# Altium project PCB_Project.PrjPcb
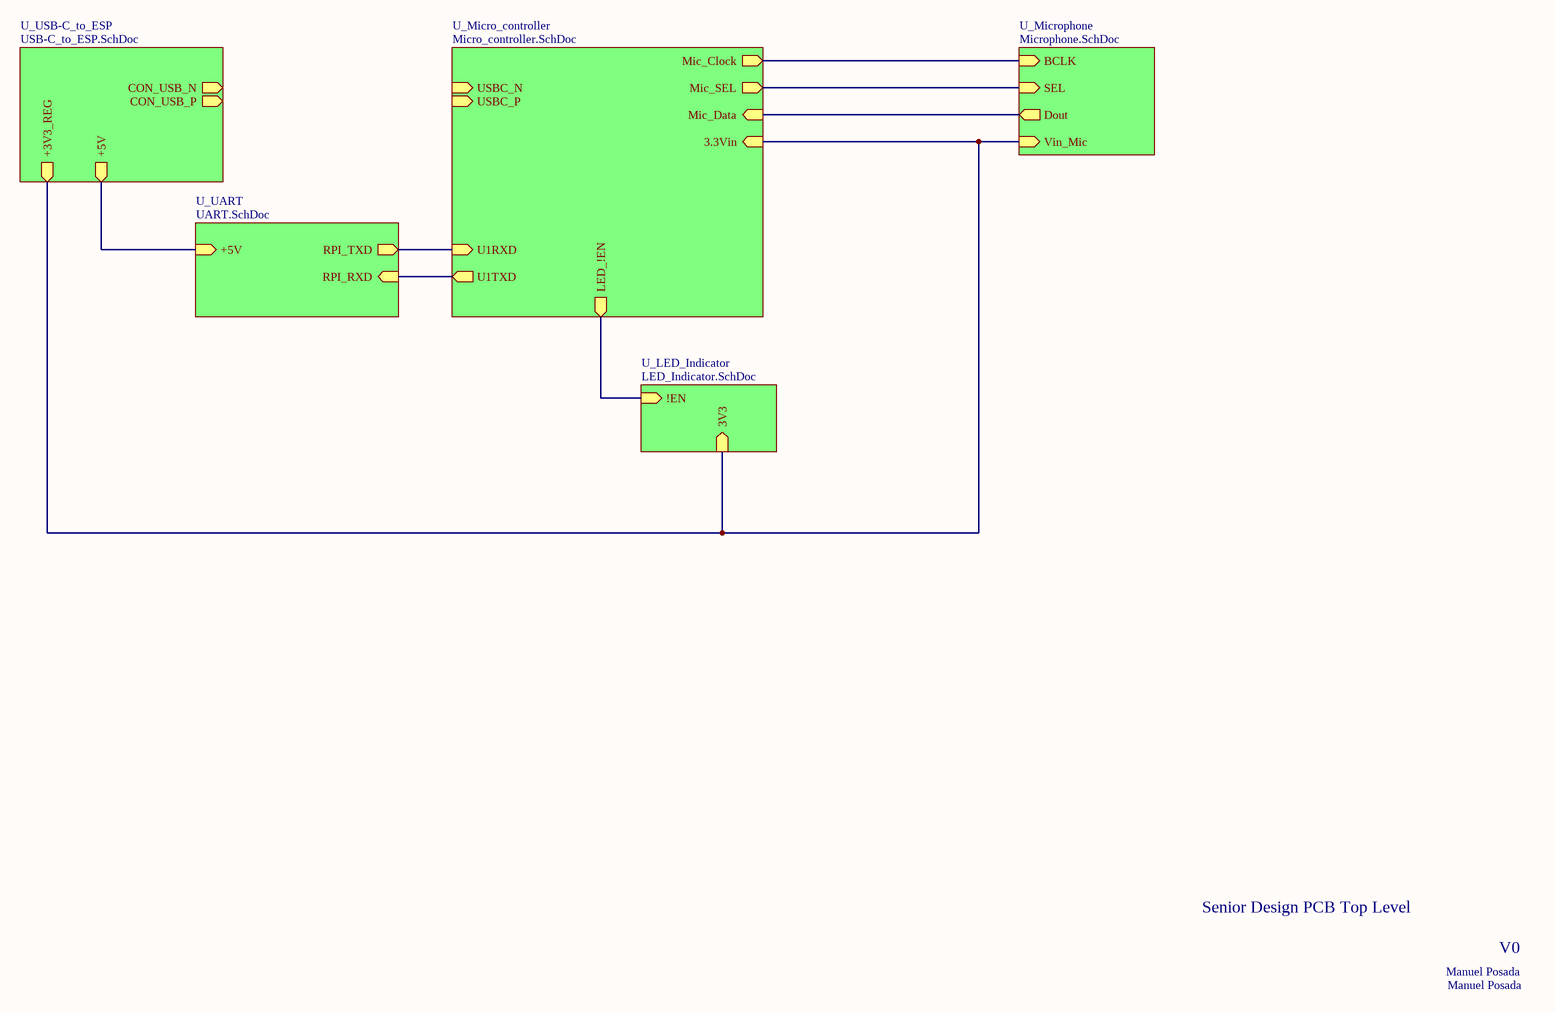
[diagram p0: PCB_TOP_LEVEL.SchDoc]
6 sheets, 64 parts. Net scope: hierarchical (ports join the sheet entries above them; power ports are global).
Sheets:
  PCB_TOP_LEVEL.SchDoc
    U_Micro_controller = Micro_controller.SchDoc
    U_USB-C_to_ESP = USB-C_to_ESP.SchDoc
    U_Microphone = Microphone.SchDoc
    U_UART = UART.SchDoc
    U_LED_Indicator = LED_Indicator.SchDoc

## Sheet PCB_TOP_LEVEL.SchDoc
size B; SheetNumber: 1; SheetTotal: 6

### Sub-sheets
U_LED_Indicator = LED_Indicator.SchDoc: 3V3 (in), !EN (in)
U_Micro_controller = Micro_controller.SchDoc: 3.3Vin (in), Mic_Data (in), Mic_SEL (out), Mic_Clock (out), U1TXD (out), U1RXD (in), LED_!EN (out), USBC_N (in), USBC_P (in)
U_Microphone = Microphone.SchDoc: Vin_Mic (in), BCLK (in), Dout (out), SEL (in)
U_UART = UART.SchDoc: +5V (in), RPI_RXD (in), RPI_TXD (out)
U_USB-C_to_ESP = USB-C_to_ESP.SchDoc: +3V3_REG (out), +5V (out), CON_USB_N (out), CON_USB_P (out)

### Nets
+3V3_REG: sheet U_Micro_controller/3.3Vin, sheet U_USB-C_to_ESP/+3V3_REG, sheet U_Microphone/Vin_Mic, sheet U_LED_Indicator/3V3
GPIO3: sheet U_Micro_controller/LED_!EN, sheet U_LED_Indicator/!EN
GPIO4: sheet U_Micro_controller/Mic_Data, sheet U_Microphone/Dout
GPIO5: sheet U_Micro_controller/Mic_SEL, sheet U_Microphone/SEL
GPIO17: sheet U_Micro_controller/U1TXD, sheet U_UART/RPI_RXD
GPIO18: sheet U_Micro_controller/U1RXD, sheet U_UART/RPI_TXD
GPIO41: sheet U_Micro_controller/Mic_Clock, sheet U_Microphone/BCLK
NetJ4_1: sheet U_USB-C_to_ESP/+5V, sheet U_UART/+5V

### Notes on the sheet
- Senior Design PCB Top Level
- Manuel Posada
- V0

## Sheet Micro_controller.SchDoc
size C; SheetNumber: 3; SheetTotal: 6
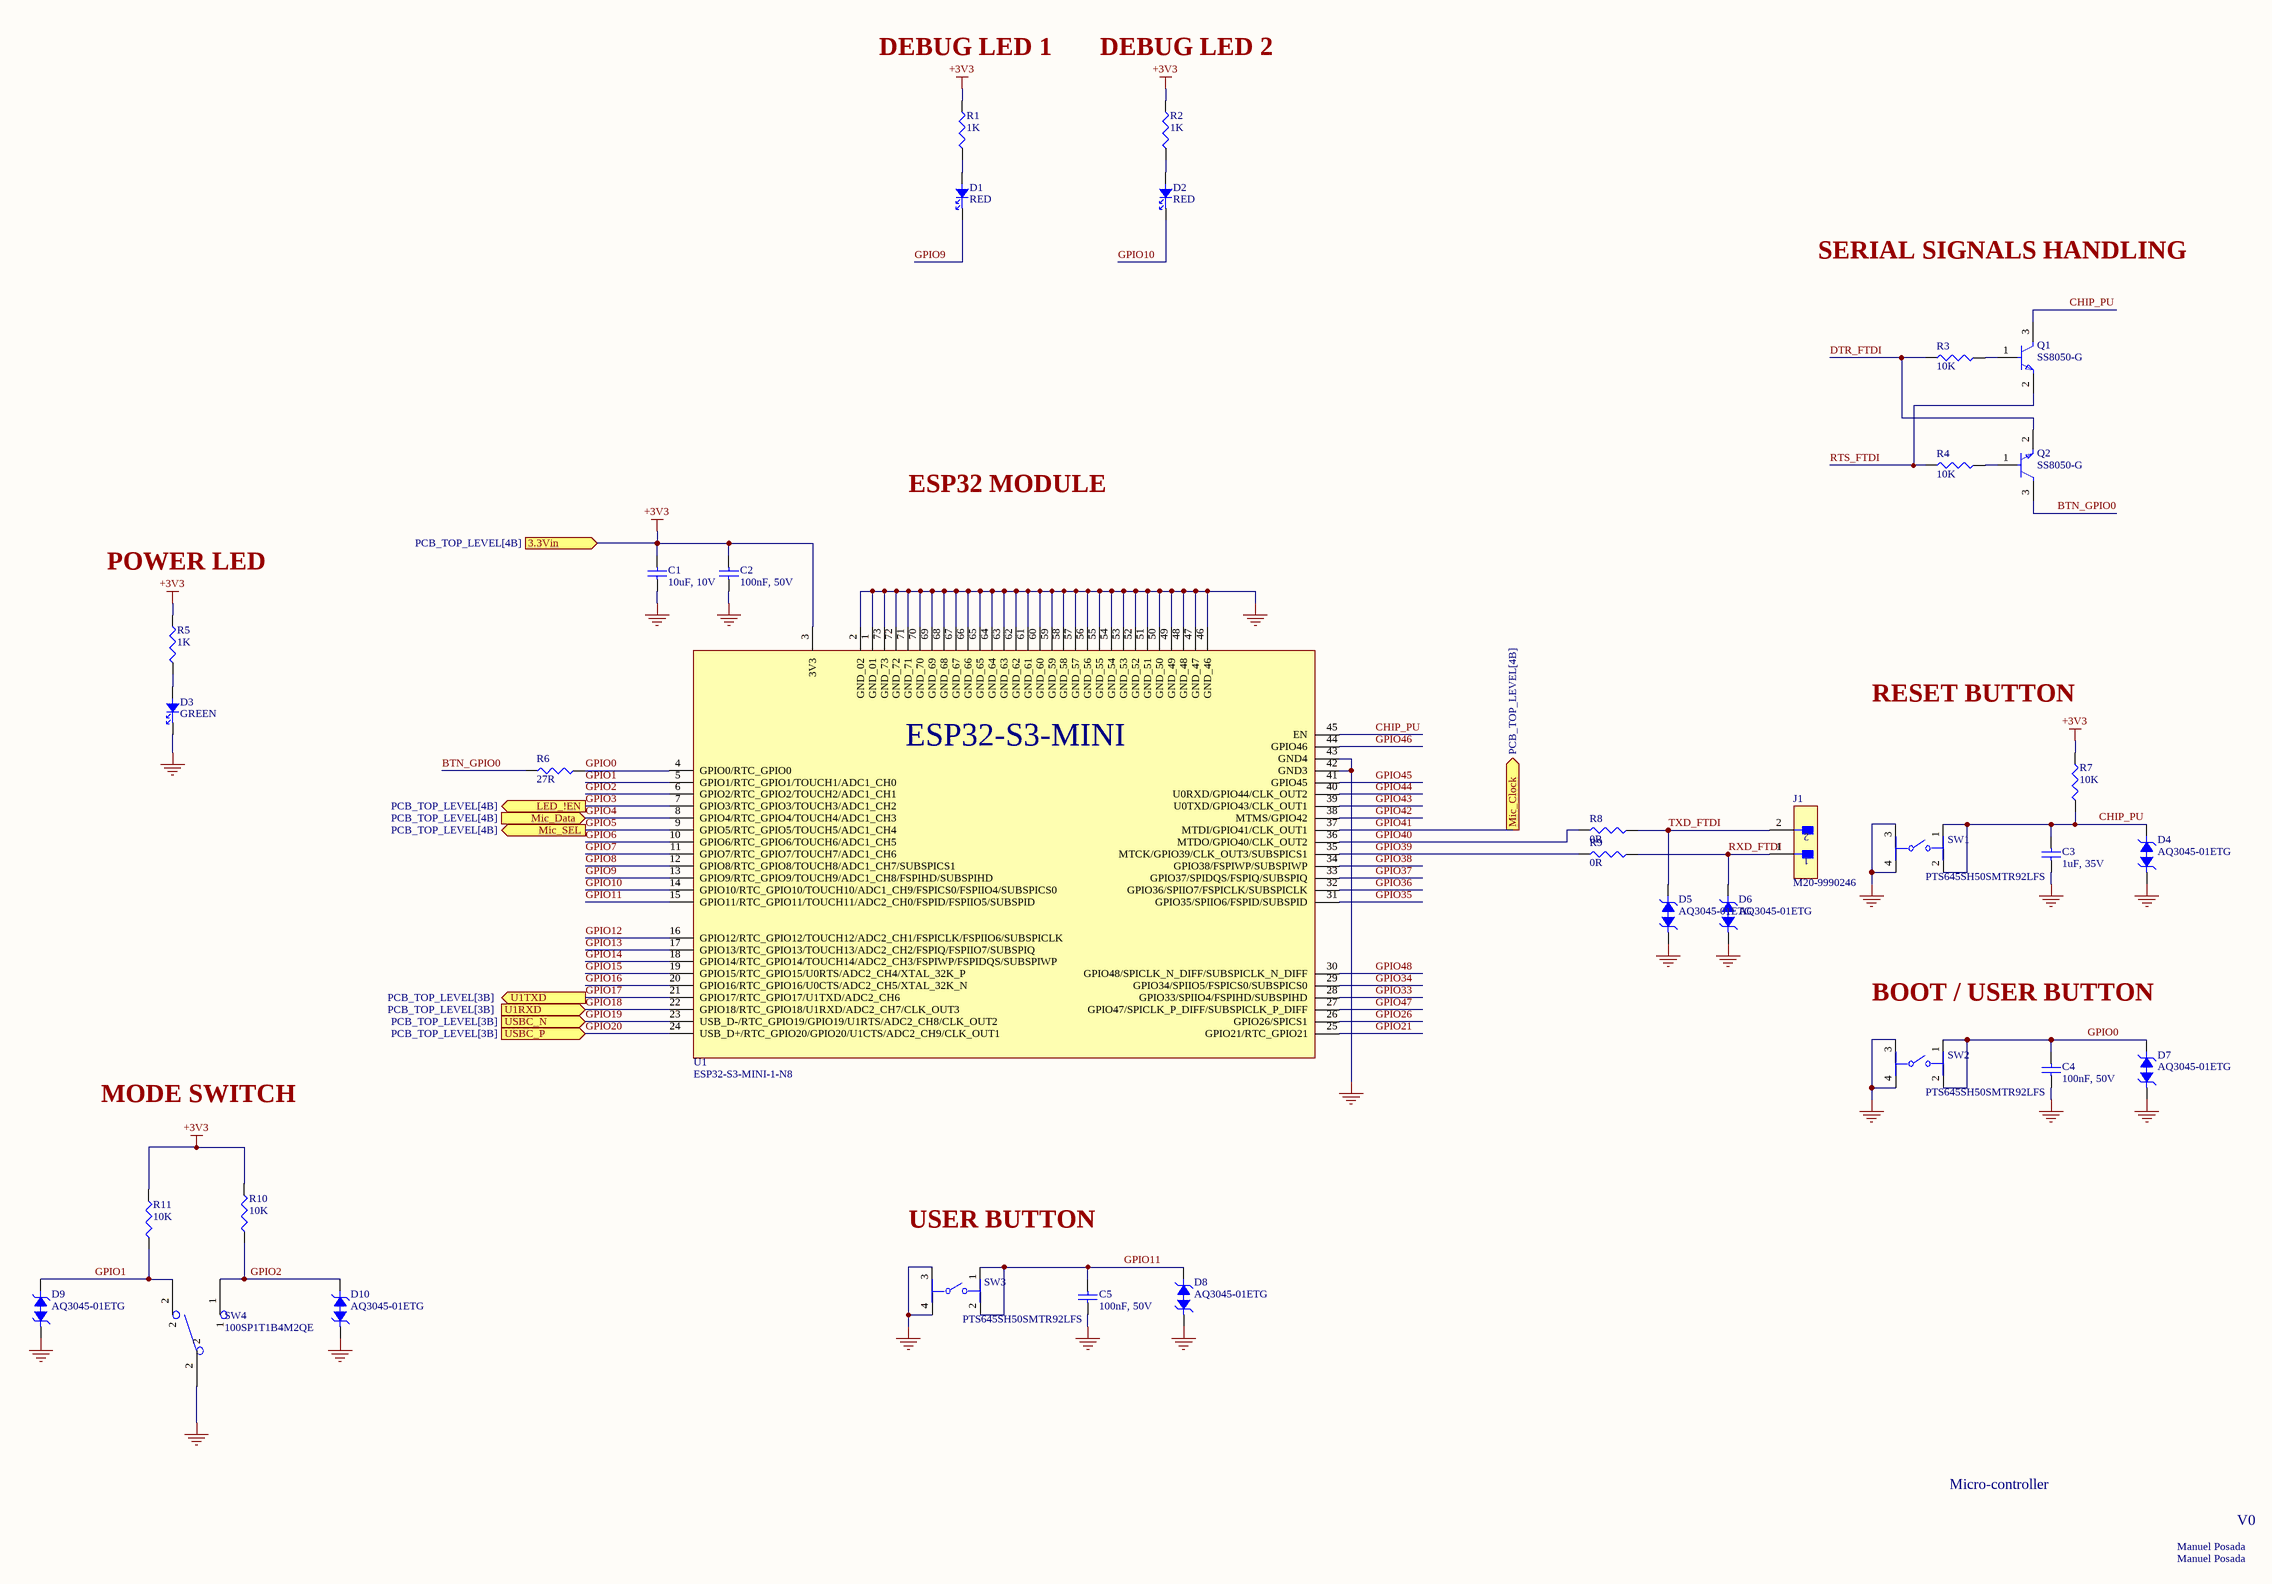
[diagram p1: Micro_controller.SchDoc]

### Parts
C1  10uF, 10V  [CAPC1005X55N]
C2  100nF, 50V  [CAPC1005X55N]
C3  1uF, 35V  [CAPC1005X55N]
C4  100nF, 50V  [CAPC1005X55N]
C5  100nF, 50V  [CAPC1005X55N]
D1  RED  [LED0402R]
D2  RED  [LED0402R]
D3  GREEN  [LED0402G]
D4  AQ3045-01ETG  [SOD882]
D5  AQ3045-01ETG  [SOD882]
D6  AQ3045-01ETG  [SOD882]
D7  AQ3045-01ETG  [SOD882]
D8  AQ3045-01ETG  [SOD882]
D9  AQ3045-01ETG  [SOD882]
D10  AQ3045-01ETG  [SOD882]
J1  M20-9990246
Q1  SS8050-G  [FP-SS8050-G-IPC_B]
Q2  SS8050-G  [FP-SS8050-G-IPC_B]
R1  1K  [RESC1005X37N]
R2  1K  [RESC1005X37N]
R3  10K  [RESC1005X37N]
R4  10K  [RESC1005X37N]
R5  1K  [RESC1005X37N]
R6  27R  [RESC1005X37N]
R7  10K  [RESC1005X37N]
R8  0R  [RESC1005X37N]
R9  0R  [RESC1005X37N]
R10  10K  [RESC1005X37N]
R11  10K  [RESC1005X37N]
SW1  PTS645SH50SMTR92LFS  [FP-PTS645SH50SMTR92LFS-MFG]
SW2  PTS645SH50SMTR92LFS  [FP-PTS645SH50SMTR92LFS-MFG]
SW3  PTS645SH50SMTR92LFS  [FP-PTS645SH50SMTR92LFS-MFG]
SW4  100SP1T1B4M2QE
U1  ESP32-S3-MINI-1-N8  [XCVR_ESP32-S3-MINI-1-N8]

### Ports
3.3Vin (in, see PCB_TOP_LEVEL[4B]), LED_!EN (out, see PCB_TOP_LEVEL[4B]), Mic_Clock (out, see PCB_TOP_LEVEL[4B]), Mic_Data (in, see PCB_TOP_LEVEL[4B]), Mic_SEL (out, see PCB_TOP_LEVEL[4B]), U1RXD (in, see PCB_TOP_LEVEL[3B]), U1TXD (out, see PCB_TOP_LEVEL[3B]), USBC_N (in, see PCB_TOP_LEVEL[3B]), USBC_P (in, see PCB_TOP_LEVEL[3B])

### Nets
+3V3: C1.2 C2.2 R1.2 R2.2 R5.2 R7.2 R10.1 R11.1 U1.3(3V3) ; port 3.3Vin  [project net +3V3_REG]
GND: C1.1 C2.1 C3.1 C4.1 C5.1 D3.1 D4.1 D5.1 D6.1 D7.1 D8.1 D9.1 D10.1 SW1.3 SW1.4 SW2.3 SW2.4 SW3.3 SW3.4 SW4.2 U1.1(GND_01) U1.2(GND_02) U1.42(GND3) U1.43(GND4) U1.46(GND_46) U1.47(GND_47) U1.48(GND_48) U1.49(GND_49) U1.50(GND_50) U1.51(GND_51) U1.52(GND_52) U1.53(GND_53) U1.54(GND_54) U1.55(GND_55) U1.56(GND_56) U1.57(GND_57) U1.58(GND_58) U1.59(GND_59) U1.60(GND_60) U1.61(GND_61) U1.62(GND_62) U1.63(GND_63) U1.64(GND_64) U1.65(GND_65) U1.66(GND_66) U1.67(GND_67) U1.68(GND_68) U1.69(GND_69) U1.70(GND_70) U1.71(GND_71) U1.72(GND_72) U1.73(GND_73)
BTN_GPIO0: Q2.3(C) R6.1
CHIP_PU: C3.2 D4.2 Q1.3(C) R7.1 SW1.1 SW1.2 U1.45(EN)
DTR_FTDI: Q2.2(E) R3.1
GPIO0: C4.2 D7.2 R6.2 SW2.1 SW2.2 U1.4(GPIO0/RTC_GPIO0)
GPIO1: D9.2 R11.2 SW4.2 U1.5(GPIO1/RTC_GPIO1/TOUCH1/ADC1_CH0)
GPIO2: D10.2 R10.2 SW4.1 U1.6(GPIO2/RTC_GPIO2/TOUCH2/ADC1_CH1)
GPIO3: U1.7(GPIO3/RTC_GPIO3/TOUCH3/ADC1_CH2) ; port LED_!EN
GPIO4: U1.8(GPIO4/RTC_GPIO4/TOUCH4/ADC1_CH3) ; port Mic_Data
GPIO5: U1.9(GPIO5/RTC_GPIO5/TOUCH5/ADC1_CH4) ; port Mic_SEL
GPIO6: U1.10(GPIO6/RTC_GPIO6/TOUCH6/ADC1_CH5)
GPIO7: U1.11(GPIO7/RTC_GPIO7/TOUCH7/ADC1_CH6)
GPIO8: U1.12(GPIO8/RTC_GPIO8/TOUCH8/ADC1_CH7/SUBSPICS1)
GPIO9: D1.1 U1.13(GPIO9/RTC_GPIO9/TOUCH9/ADC1_CH8/FSPIHD/SUBSPIHD)
GPIO10: D2.1 U1.14(GPIO10/RTC_GPIO10/TOUCH10/ADC1_CH9/FSPICS0/FSPIIO4/SUBSPICS0)
GPIO11: C5.2 D8.2 SW3.1 SW3.2 U1.15(GPIO11/RTC_GPIO11/TOUCH11/ADC2_CH0/FSPID/FSPIIO5/SUBSPID)
GPIO12: U1.16(GPIO12/RTC_GPIO12/TOUCH12/ADC2_CH1/FSPICLK/FSPIIO6/SUBSPICLK)
GPIO13: U1.17(GPIO13/RTC_GPIO13/TOUCH13/ADC2_CH2/FSPIQ/FSPIIO7/SUBSPIQ)
GPIO14: U1.18(GPIO14/RTC_GPIO14/TOUCH14/ADC2_CH3/FSPIWP/FSPIDQS/SUBSPIWP)
GPIO15: U1.19(GPIO15/RTC_GPIO15/U0RTS/ADC2_CH4/XTAL_32K_P)
GPIO16: U1.20(GPIO16/RTC_GPIO16/U0CTS/ADC2_CH5/XTAL_32K_N)
GPIO17: U1.21(GPIO17/RTC_GPIO17/U1TXD/ADC2_CH6) ; port U1TXD
GPIO18: U1.22(GPIO18/RTC_GPIO18/U1RXD/ADC2_CH7/CLK_OUT3) ; port U1RXD
GPIO19: U1.23(USB_D-/RTC_GPIO19/GPIO19/U1RTS/ADC2_CH8/CLK_OUT2) ; port USBC_N
GPIO20: U1.24(USB_D+/RTC_GPIO20/GPIO20/U1CTS/ADC2_CH9/CLK_OUT1) ; port USBC_P
GPIO21: U1.25(GPIO21/RTC_GPIO21)
GPIO26: U1.26(GPIO26/SPICS1)
GPIO33: U1.28(GPIO33/SPIIO4/FSPIHD/SUBSPIHD)
GPIO34: U1.29(GPIO34/SPIIO5/FSPICS0/SUBSPICS0)
GPIO35: U1.31(GPIO35/SPIIO6/FSPID/SUBSPID)
GPIO36: U1.32(GPIO36/SPIIO7/FSPICLK/SUBSPICLK)
GPIO37: U1.33(GPIO37/SPIDQS/FSPIQ/SUBSPIQ)
GPIO38: U1.34(GPIO38/FSPIWP/SUBSPIWP)
GPIO39: R9.1 U1.35(MTCK/GPIO39/CLK_OUT3/SUBSPICS1)
GPIO40: R8.1 U1.36(MTDO/GPIO40/CLK_OUT2)
GPIO41: U1.37(MTDI/GPIO41/CLK_OUT1) ; port Mic_Clock
GPIO42: U1.38(MTMS/GPIO42)
GPIO43: U1.39(U0TXD/GPIO43/CLK_OUT1)
GPIO44: U1.40(U0RXD/GPIO44/CLK_OUT2)
GPIO45: U1.41(GPIO45)
GPIO46: U1.44(GPIO46)
GPIO47: U1.27(GPIO47/SPICLK_P_DIFF/SUBSPICLK_P_DIFF)
GPIO48: U1.30(GPIO48/SPICLK_N_DIFF/SUBSPICLK_N_DIFF)
RTS_FTDI: Q1.2(E) R4.1
RXD_FTDI: D6.2 J1.1 R9.2
TXD_FTDI: D5.2 J1.2 R8.2
NetD1_2: D1.2 R1.1
NetD2_2: D2.2 R2.1
NetD3_2: D3.2 R5.1
NetQ1_1: Q1.1(B) R3.2
NetQ2_1: Q2.1(B) R4.2

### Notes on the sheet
- DEBUG LED 1
- DEBUG LED 2
- SERIAL SIGNALS HANDLING
- ESP32 MODULE
- POWER LED
- RESET BUTTON
- BOOT / USER BUTTON
- MODE SWITCH
- USER BUTTON
- Micro-controller
- Manuel Posada
- V0

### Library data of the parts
C1 = CL05A106MP8NUB8: CAP CER 10UF 10V X5R 0402; Manufacturer: Samsung; Dielectric Material: Ceramic; Multilayer: Yes; Tolerance  (fill in as +-): 20%
C2 C4 C5 = CL05B104KB54PNC: CAP CER 0.1UF 50V X7R 0402; Manufacturer: Samsung; Dielectric Material: Ceramic
C3 = CL05A105KL5NRNC: CAP CER 1UF 35V X5R 0402; Manufacturer: Samsung; Dielectric Material: Ceramic; Multilayer: Yes; Tolerance  (fill in as +-): 10%
D1 D2 = VLMS1500-GS08: LED RED 0402 SMD; Manufacturer: Vishay; Shape: Rectangular; Forward Current: 30mA; Forward Voltage: 2.4V; Luminous Intensity-Nom: 54mcd; Channels: 1; Optoelectronic Device Type: SINGLE COLOR LED; Reverse Voltage-Max: 5V; Viewing Angle: 130°; Overall Height: 0.35mm
D3 = VLMG1500-GS08: LED YLW-GRN 0402 SMD; Manufacturer: Vishay; Color: Green,Yellow; Lens Color: Clear; Viewing Angle: 130°; Forward Current: 30mA; Forward Voltage: 2V; Luminous Intensity: 35mcd; Dominant Wavelength: 571nm; Test Current: 20mA; Number of Elements: 1; Power Dissipation: 75mW; Lens Style: Rectangular; Reverse Voltage: 5V
D4-D10 = AQ3045-01ETG: TVS DIODE 5.3VWM 12VC SOD882; Manufacturer: Littelfuse; Diode Element Material: SILICON; Package Body Material: Plastic; Polarity: Bidirectional; Max Breakdown Voltage: 9V; Min Breakdown Voltage: 6.8V; Diode Type: TRANS VOLTAGE SUPPRESSOR; Non-rep Peak Rev Power Dis-Max: 40W; Number of Elements: 1; Rep Pk Reverse Voltage-Max: 5.3V; Reference Standard: AEC-Q101
J1 = M20-9990246: Connector Header Through Hole 2 position 0.100" (2.54mm); Manufacturer: Harwin; Connector Type: Male Pin; Contact Resistance: 30mΩ; Current Rating: 3A; Dielectric Material: Polyamide; Gender: Male; Insulation Resistance: 1GΩ; Number of Contacts: 2; Voltage Rating (AC): 750V
Q1 Q2 = SS8050-G: TRANS NPN 25V 1.5A SOT23-3; Manufacturer: Comchip
R1 R2 R5 = RC0402FR-071KL: RES 1K OHM 1% 1/16W 0402; Manufacturer: Yageo; Additional Feature: LASER TRIMMABLE; Power: 62.5mW; Rated Temperature: 70°C; Value: 1kR; Temperature Coefficient: 100ppm/°C; Working Voltage: 50V; Package Height: 0.35mm; Package Length: 1mm; Package Width: 0.5mm
R3 R4 R7 R10 R11 = AC0402FR-0710KL: RES SMD 10K OHM 1% 1/16W 0402; Manufacturer: Yageo; Additional Feature: LASER TRIMMABLE; Power: 62.5mW; Rated Temperature: 70°C; Value: 10kR; Temperature Coefficient: 100ppm/°C; Working Voltage: 50V; Package Height: 0.32mm; Package Length: 1mm; Package Width: 0.5mm; Reference Standard: AEC-Q200
R6 = RC0402FR-0727RL: RES 27 OHM 1% 1/16W 0402; Manufacturer: Yageo; Additional Feature: LASER TRIMMABLE; Power: 62.5mW; Rated Temperature: 70°C; Temperature Coefficient: 100ppm/°C; Working Voltage: 50V; Package Height: 0.35mm; Package Length: 1mm; Package Width: 0.5mm
R8 R9 = RC0402JR-070RL: RES 0 OHM JUMPER 1/16W 0402; Manufacturer: Yageo; Power: 62.5mW; Rated Temperature: 70°C; Package Height: 0.35mm; Package Length: 1mm; Package Width: 0.5mm
SW1-SW3 = PTS645SH50SMTR92LFS: SWITCH TACTILE SPST-NO 0.05A 12V; Manufacturer: ITT C&K; Manufacturer Series: PTS645; Actuator Type: Pushbutton; Contact Current(DC)-Max: 50mA; Contact DC Max Rating R Load: 0.05A@12VDC; Contact Resistance: 0.1mR; Dielectric Withstand Volts: 250VACV; Electrical Life: 100000Cycles; Insulation Resistance: 100GR; PCB Hole Count: 4; Switch Action: MOMENTARY; Switch Function: SPST; Switch Type: Keypad; Body Breadth: 5.9944inch; Body Height: 3.4544mm; Body Length or Diameter: 5.9944mm
SW4 = 100SP1T1B4M2QE: Switch Toggle ON None ON SPDT Round Lever PC Pins 5A 250VAC 28VDC PC Mount; Manufacturer: E-Switch; Actuator Length: 10.414mm; Actuator Material: Brass, Chrome; Contact Voltage Rating (AC): 120V; Electrical Life: 50kcycles; Illumination Type: Illuminated, Non-Illuminated; Max Voltage Rating (DC): 28V; Number of Positions: 2; Sealable: EPOXY TERMINAL SEALED; Switch Function: On-On
U1 = ESP32-S3-MINI-1-N8: SMD Module, ESP32-S3FN8, 8 mb Sp; Manufacturer: Espressif Systems

## Sheet USB-C_to_ESP.SchDoc
size B; SheetNumber: 2; SheetTotal: 6
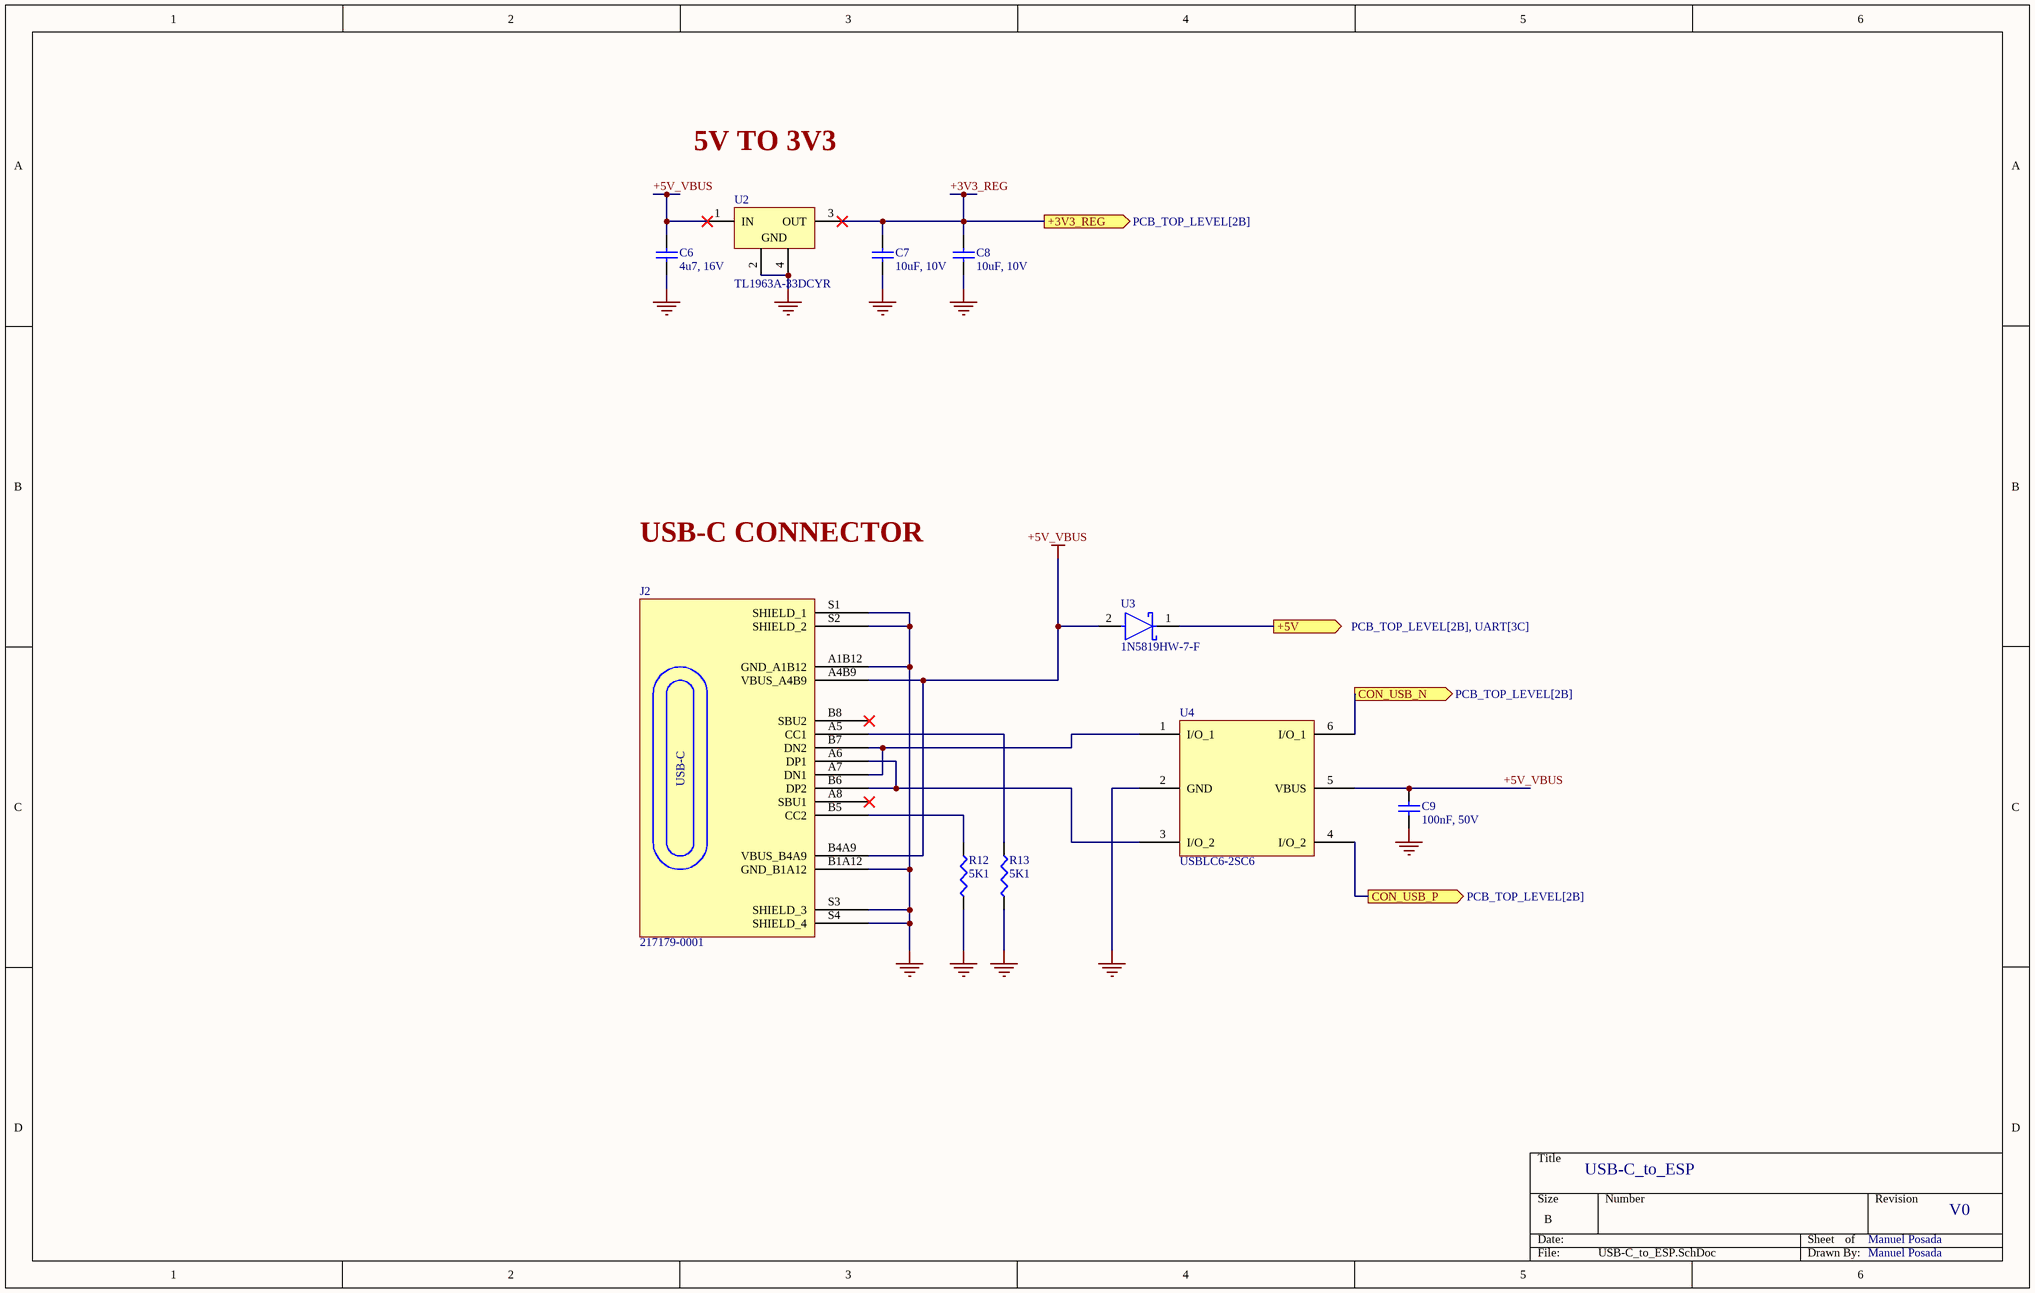
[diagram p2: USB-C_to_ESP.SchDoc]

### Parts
C6  4u7, 16V  [CAPC1005X55N]
C7  10uF, 10V  [CAPC1005X55N]
C8  10uF, 10V  [CAPC1005X55N]
C9  100nF, 50V  [CAPC1005X55N]
J2  217179-0001  [FP-2171790001-MFG]
R12  5K1  [RESC1005X37N]
R13  5K1  [RESC1005X37N]
U2  TL1963A-33DCYR  [DCY0004A_N]
U3  1N5819HW-7-F
U4  USBLC6-2SC6

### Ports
+3V3_REG (out, see PCB_TOP_LEVEL[2B]), +5V (out, see PCB_TOP_LEVEL[2B], UART[3C]), CON_USB_N (out, see PCB_TOP_LEVEL[2B]), CON_USB_P (out, see PCB_TOP_LEVEL[2B])

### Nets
+3V3_REG: C7.2 C8.2 U2.3(OUT) ; port +3V3_REG
+5V_VBUS: C6.2 C9.2 J2.A4B9(VBUS_A4B9) J2.B4A9(VBUS_B4A9) U2.1(IN) U3.2(A) U4.5(VBUS)
GND: C6.1 C7.1 C8.1 C9.1 J2.A1B12(GND_A1B12) J2.B1A12(GND_B1A12) J2.S1(SHIELD_1) J2.S2(SHIELD_2) J2.S3(SHIELD_3) J2.S4(SHIELD_4) R12.1 R13.1 U2.2(GND) U2.4(GND) U4.2(GND)
NetJ2_A5: J2.A5(CC1) R13.2
NetJ2_A6: J2.A6(DP1) J2.B6(DP2) U4.3(I/O_2)
NetJ2_A7: J2.A7(DN1) J2.B7(DN2) U4.1(I/O_1)
NetJ2_B5: J2.B5(CC2) R12.2
NetJ4_1: U3.1(C) ; port +5V
NetU4_4: U4.4(I/O_2) ; port CON_USB_P
NetU4_6: U4.6(I/O_1) ; port CON_USB_N

Not connected (* = marked no-connect by the designer): J2 A8(SBU1)* B8(SBU2)*

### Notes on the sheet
- 5V TO 3V3
- USB-C CONNECTOR
- USB-C_to_ESP
- Manuel Posada
- V0

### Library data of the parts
C6 = CL05A475MO5NUNC: CAP CER 4.7UF 16V X5R 0402; Manufacturer: Samsung; Dielectric Material: Ceramic; Multilayer: Yes; Tolerance  (fill in as +-): 20%
C7 C8 = CL05A106MP8NUB8: as C1 on sheet Micro_controller
C9 = CL05B104KB54PNC: as C2 on sheet Micro_controller
J2 = 217179-0001: CONN RCP USB2.0 TYP C 24P SMD RA; Manufacturer: Molex
R12 R13 = AC0402FR-075K1L: RES SMD 5.1K OHM 1% 1/16W 0402; Manufacturer: Yageo; Additional Feature: LASER TRIMMABLE; Power: 62.5mW; Rated Temperature: 70°C; Value: 5.1kR; Temperature Coefficient: 100ppm/°C; Working Voltage: 50V; Package Height: 0.32mm; Package Length: 1mm; Package Width: 0.5mm; Reference Standard: AEC-Q200
U2 = TL1963A-33DCYR: IC REG LINEAR 3.3V 1.5A SOT223-4; Manufacturer: Texas Instruments; Package Body Material: Plastic; Adjustability: FIXED; Dropout Voltage1-Max: 550mV; Dropout Voltage1-Nom: 340mV; Input Voltage Absolute-Max: 20V; Min Input Voltage: 3.8V; Line Regulation-Max: 0.01%; Load Regulation-Max: 0.07%; Channels: 1; Output Voltage1-Max: 3.4V; Output Voltage1-Min: 3.2V; Regulator Type: FIXED POSITIVE SINGLE OUTPUT LDO REGULATOR; Voltage Tolerance-Max: 3%; Qualification Status: Not Qualified
U3 = 1N5819HW-7-F: DIODE SCHOTTKY 40V 1A SOD123; Manufacturer: Diodes Inc.; Value: 50pF; Element Configuration: Single; Forward Voltage: 750mV; Max Forward Surge Current (Ifsm): 25A; Max Junction Temperature (Tj): 125°C; Max Power Dissipation: 450mW; Number of Elements: 1; Peak Reverse Current: 1mA; Polarity: Standard
U4 = USBLC6-2SC6: 17V Clamp 5A (8/20µs) Ipp Tvs Diode Surface Mount SOT-23-6; Manufacturer: STMicroelectronics; Breakdown Voltage: 6V; Value: 2.5pF; Data Rate: 480Mbps; Direction: Unidirectional; Element Configuration: Dual; ESD Protection: Yes; Forward Voltage: 1.1V; Leakage Current: 150nA; Max Junction Temperature (Tj): 125°C; Max Repetitive Reverse Voltage (Vrrm): 5.25V; Number of Bidirectional Channels: 2; Number of Elements: 1; Reverse Standoff Voltage: 5V; Test Current: 1mA

## Sheet Microphone.SchDoc
size A; SheetNumber: 4; SheetTotal: 6
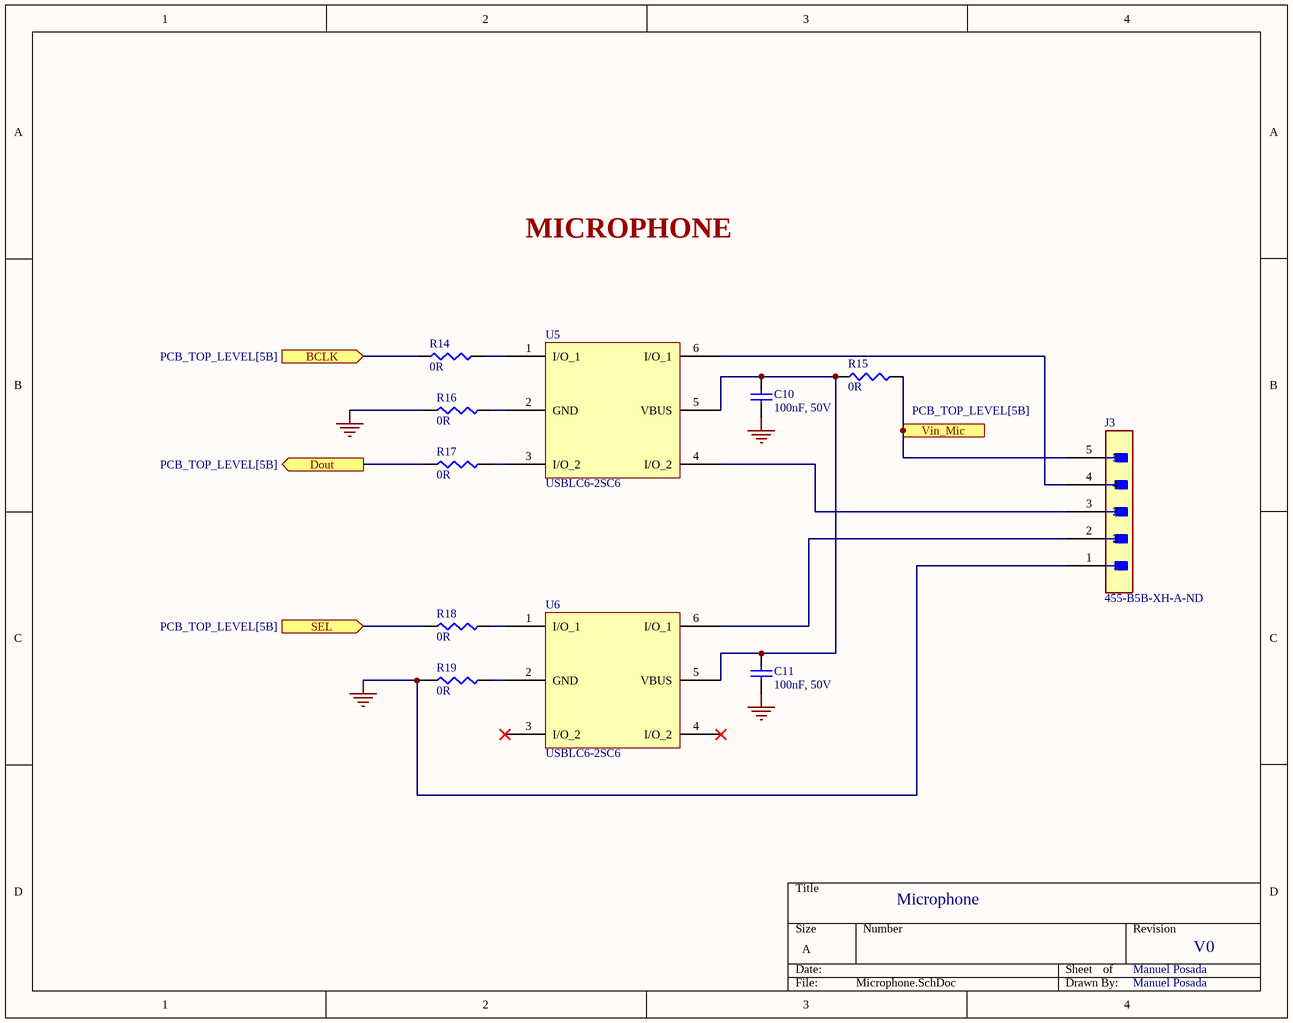
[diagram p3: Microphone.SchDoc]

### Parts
C10  100nF, 50V  [CAPC1005X55N]
C11  100nF, 50V  [CAPC1005X55N]
J3  455-B5B-XH-A-ND
R14  0R  [RESC1005X37N]
R15  0R  [RESC1005X37N]
R16  0R  [RESC1005X37N]
R17  0R  [RESC1005X37N]
R18  0R  [RESC1005X37N]
R19  0R  [RESC1005X37N]
U5  USBLC6-2SC6
U6  USBLC6-2SC6

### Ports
BCLK (in, see PCB_TOP_LEVEL[5B]), Dout (out, see PCB_TOP_LEVEL[5B]), SEL (in, see PCB_TOP_LEVEL[5B]), Vin_Mic (in, see PCB_TOP_LEVEL[5B])

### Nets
+3V3_REG: J3.5 R15.2 ; port Vin_Mic
GND: C10.2 C11.2 J3.1 R16.1 R19.1
GPIO4: R17.1 ; port Dout
GPIO5: R18.1 ; port SEL
GPIO41: R14.1 ; port BCLK
NetC10_1: C10.1 C11.1 R15.1 U5.5(VBUS) U6.5(VBUS)
NetJ3_2: J3.2 U6.6(I/O_1)
NetJ3_3: J3.3 U5.4(I/O_2)
NetJ3_4: J3.4 U5.6(I/O_1)
NetR14_2: R14.2 U5.1(I/O_1)
NetR16_2: R16.2 U5.2(GND)
NetR17_2: R17.2 U5.3(I/O_2)
NetR18_2: R18.2 U6.1(I/O_1)
NetR19_2: R19.2 U6.2(GND)

Not connected (* = marked no-connect by the designer): U6 3(I/O_2)* 4(I/O_2)*

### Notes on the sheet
- MICROPHONE
- Microphone
- Manuel Posada
- V0

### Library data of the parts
C10 C11 = CL05B104KB54PNC: as C2 on sheet Micro_controller
J3 = B5B-XH-A: Board Connector, 5 Contact(s), 1 Row(s), Male, Straight, 0.098 inch Pitch, Solder Terminal; Manufacturer: JST; Contact Resistance: 20mΩ; Current Rating: 3A; Insulation Resistance: 1GΩ
R14-R19 = RC0402JR-070RL: as R8 on sheet Micro_controller
U5 U6 = USBLC6-2SC6: as U4 on sheet USB-C_to_ESP

## Sheet UART.SchDoc
size A; SheetNumber: 5; SheetTotal: 6
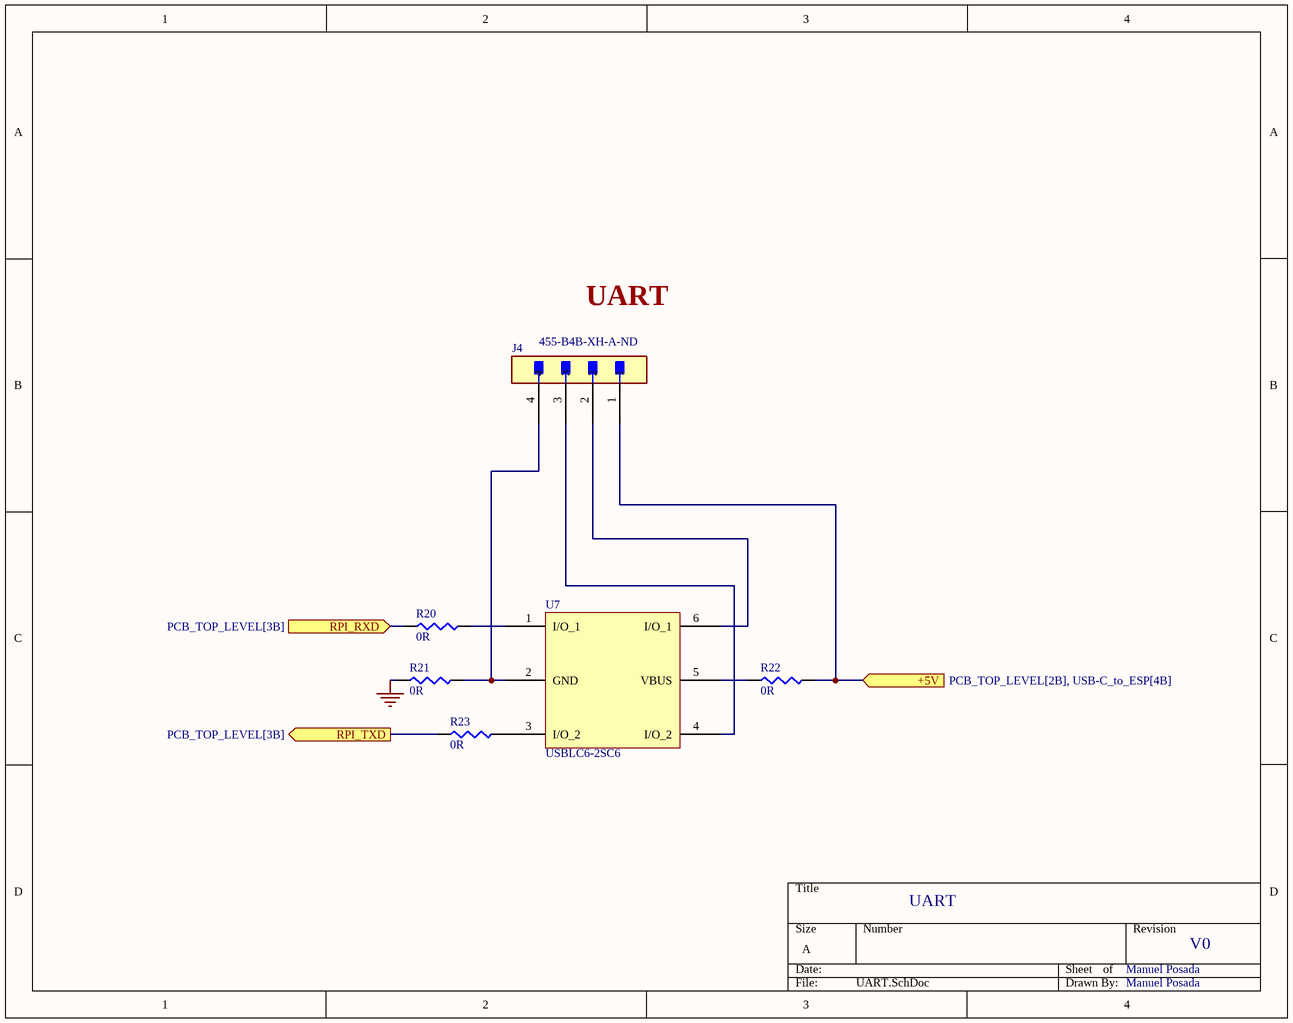
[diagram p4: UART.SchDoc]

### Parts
J4  455-B4B-XH-A-ND
R20  0R  [RESC1005X37N]
R21  0R  [RESC1005X37N]
R22  0R  [RESC1005X37N]
R23  0R  [RESC1005X37N]
U7  USBLC6-2SC6

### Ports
+5V (in, see PCB_TOP_LEVEL[2B], USB-C_to_ESP[4B]), RPI_RXD (in, see PCB_TOP_LEVEL[3B]), RPI_TXD (out, see PCB_TOP_LEVEL[3B])

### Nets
GND: R21.1
GPIO17: R20.1 ; port RPI_RXD
GPIO18: R23.1 ; port RPI_TXD
NetJ4_1: J4.1 R22.1 ; port +5V
NetJ4_2: J4.2 U7.6(I/O_1)
NetJ4_3: J4.3 U7.4(I/O_2)
NetJ4_4: J4.4 R21.2 U7.2(GND)
NetR20_2: R20.2 U7.1(I/O_1)
NetR22_2: R22.2 U7.5(VBUS)
NetR23_2: R23.2 U7.3(I/O_2)

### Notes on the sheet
- UART
- Manuel Posada
- V0

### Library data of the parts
J4 = B4B-XH-A: Board Connector, 4 Contact(s), 1 Row(s), Male, Straight, Solder Terminal; Manufacturer: JST; Contact Resistance: 20mΩ; Current Rating: 3A; Insulation Resistance: 1GΩ
R20-R23 = RC0402JR-070RL: as R8 on sheet Micro_controller
U7 = USBLC6-2SC6: as U4 on sheet USB-C_to_ESP

## Sheet LED_Indicator.SchDoc
size A; SheetNumber: 6; SheetTotal: 6
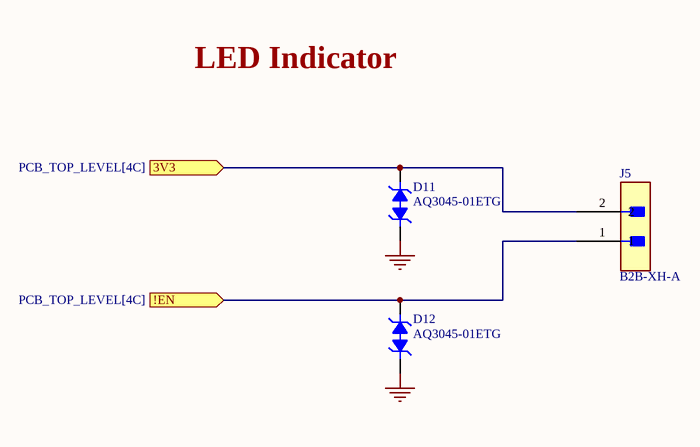
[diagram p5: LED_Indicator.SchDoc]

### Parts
D11  AQ3045-01ETG  [SOD882]
D12  AQ3045-01ETG  [SOD882]
J5  B2B-XH-A

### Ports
3V3 (in, see PCB_TOP_LEVEL[4C]), !EN (in, see PCB_TOP_LEVEL[4C])

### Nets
+3V3_REG: D11.2 J5.2 ; port 3V3
GND: D11.1 D12.1
GPIO3: D12.2 J5.1 ; port !EN

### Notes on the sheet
- LED Indicator

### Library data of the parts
D11 D12 = AQ3045-01ETG: as D4 on sheet Micro_controller
J5 = B2B-XH-A: Board Connector, 2 Contact(s), 1 Row(s), Male, Straight, Solder Terminal; Manufacturer: JST; Contact Resistance: 20mΩ; Current Rating: 3A; Insulation Resistance: 1GΩ

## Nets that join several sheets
+3V3_REG: Micro_controller (9 pins), USB-C_to_ESP (C7.2 C8.2 U2.3), Microphone (J3.5 R15.2), LED_Indicator (D11.2 J5.2)
GND: Micro_controller (52 pins), USB-C_to_ESP (15 pins), Microphone (5 pins), UART (R21.1), LED_Indicator (D11.1 D12.1)
GPIO3: Micro_controller (U1.7), LED_Indicator (D12.2 J5.1)
GPIO4: Micro_controller (U1.8), Microphone (R17.1)
GPIO5: Micro_controller (U1.9), Microphone (R18.1)
GPIO17: Micro_controller (U1.21), UART (R20.1)
GPIO18: Micro_controller (U1.22), UART (R23.1)
GPIO41: Micro_controller (U1.37), Microphone (R14.1)
NetJ4_1: USB-C_to_ESP (U3.1), UART (J4.1 R22.1)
